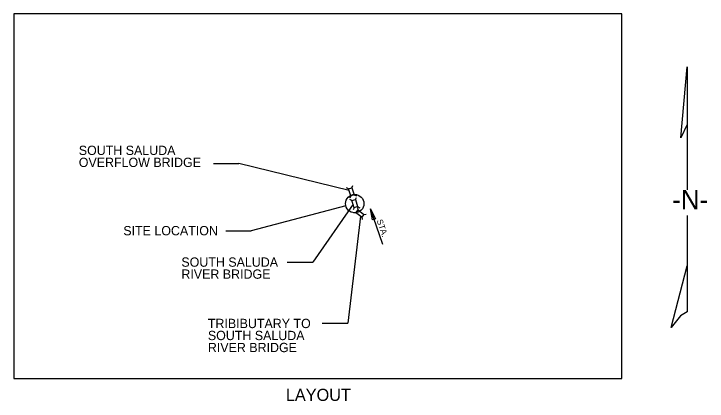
# Model space of a CAD drawing. Extents: x -4.82 to 4.15, y -0.44 to 2.32.
# Drawn here: x 2.958 to 4.146, y 0.505 to 1.169 of the extents above; entities that cross this region are included whole.
import ezdxf

# ---------------------------------------------------------------- set-up
doc = ezdxf.new("R2010")
doc.units = 0
for name, color, linetype in [('BR_AUTO DIMENSION', 7, 'Continuous'), ('BR_BORDER LINES', 7, 'Continuous'), ('BR_TEXT', 7, 'Continuous'), ('Default', 7, 'Continuous')]:
    doc.layers.add(name, color=color, linetype=linetype)

msp = doc.modelspace()

# ---------------------------------------------------------------- linework, layer by layer
at = {"layer": 'BR_AUTO DIMENSION'}
for p, q in [((3.3004, 0.9123), (3.3441, 0.9123)), ((3.5328, 0.8658), (3.3441, 0.9123)), ((3.5273, 0.8395), (3.3652, 0.797)), ((3.5396, 0.8425), (3.4704, 0.743)), ((3.5521, 0.8219), (3.5304, 0.6384)), ((3.3214, 0.797), (3.3652, 0.797)), ((3.4266, 0.743), (3.4704, 0.743)), ((3.4866, 0.6384), (3.5304, 0.6384))]:
    msp.add_line(p, q, dxfattribs=at)
msp.add_circle((3.5425, 0.8434), 0.0157, dxfattribs=at)
at = {"layer": 'BR_BORDER LINES'}
msp.add_lwpolyline([(2.9583, 0.5438), (4, 0.5438), (4, 1.1688), (2.9583, 1.1688)], close=True, dxfattribs=at)
at = {"layer": 'BR_TEXT'}
for p, q in [((3.5318, 0.8688), (3.5282, 0.8707)), ((3.5377, 0.8707), (3.5394, 0.8744)), ((3.5358, 0.8566), (3.534, 0.853)), ((3.5416, 0.8585), (3.5452, 0.8566)), ((3.5376, 0.8485), (3.534, 0.8505)), ((3.5435, 0.8504), (3.5452, 0.8541)), ((3.5415, 0.8364), (3.5398, 0.8327)), ((3.5474, 0.8383), (3.551, 0.8363)), ((3.5481, 0.8327), (3.5475, 0.8368)), ((3.5904, 0.7736), (3.5695, 0.8344)), ((3.5443, 0.8279), (3.5403, 0.8274)), ((3.5545, 0.82), (3.5551, 0.816)), ((3.5582, 0.8249), (3.5623, 0.8253))]:
    msp.add_line(p, q, dxfattribs=at)
for points in [[(3.5416, 0.8585), (3.5358, 0.8566), (3.5318, 0.8688), (3.5377, 0.8707)], [(3.5474, 0.8383), (3.5415, 0.8364), (3.5376, 0.8485), (3.5435, 0.8504)], [(3.5582, 0.8249), (3.5545, 0.82), (3.5443, 0.8279), (3.5481, 0.8327)], [(3.5729, 0.8158), (3.5695, 0.8344), (3.5782, 0.8176)]]:
    msp.add_lwpolyline(points, close=True, dxfattribs=at)
at = {"layer": 'Default'}
for p, q in [((4.1013, 0.9564), (4.1124, 1.0778)), ((4.1124, 1.0778), (4.1124, 0.979)), ((4.1124, 0.979), (4.1013, 0.9564)), ((4.1124, 0.979), (4.1124, 0.9105)), ((4.1124, 0.9105), (4.1124, 0.8668)), ((4.1124, 0.8232), (4.1124, 0.7369)), ((4.0849, 0.6311), (4.1124, 0.7369)), ((4.1124, 0.7369), (4.1124, 0.7238)), ((4.1124, 0.7238), (4.1124, 0.6577))]:
    msp.add_line(p, q, dxfattribs=at)
msp.add_lwpolyline([(4.1124, 0.6577), (4.1006, 0.6512), (4.0849, 0.6311)], dxfattribs=at)

# ---------------------------------------------------------------- texts
at = {"layer": 'BR_TEXT'}
for s, height, rotation, p in [('SOUTH SALUDA ', 0.015922, 360, (3.0696, 0.9268)), ('OVERFLOW BRIDGE', 0.015922, 360, (3.0696, 0.9062)), ('STA.', 0.01042, 289.0112, (3.5798, 0.8145)), ('SITE LOCATION ', 0.015922, 360, (3.1459, 0.7891)), ('SOUTH SALUDA ', 0.015922, 360, (3.2454, 0.7352)), ('RIVER BRIDGE', 0.015922, 360, (3.2454, 0.7146)), ('TRIBIBUTARY TO ', 0.015922, 360, (3.2908, 0.63)), ('SOUTH SALUDA ', 0.015922, 360, (3.2908, 0.6094)), ('RIVER BRIDGE', 0.015922, 360, (3.2908, 0.5888))]:
    msp.add_text(s, height=height, rotation=rotation, dxfattribs=at).set_placement(p)
at = {"layer": 'Default'}
for s, height, p in [('-N-', 0.03333, (4.0864, 0.8337)), ('LAYOUT', 0.02083, (3.4244, 0.5051))]:
    msp.add_text(s, height=height, dxfattribs=at).set_placement(p)

doc.saveas('drawing.dxf')
